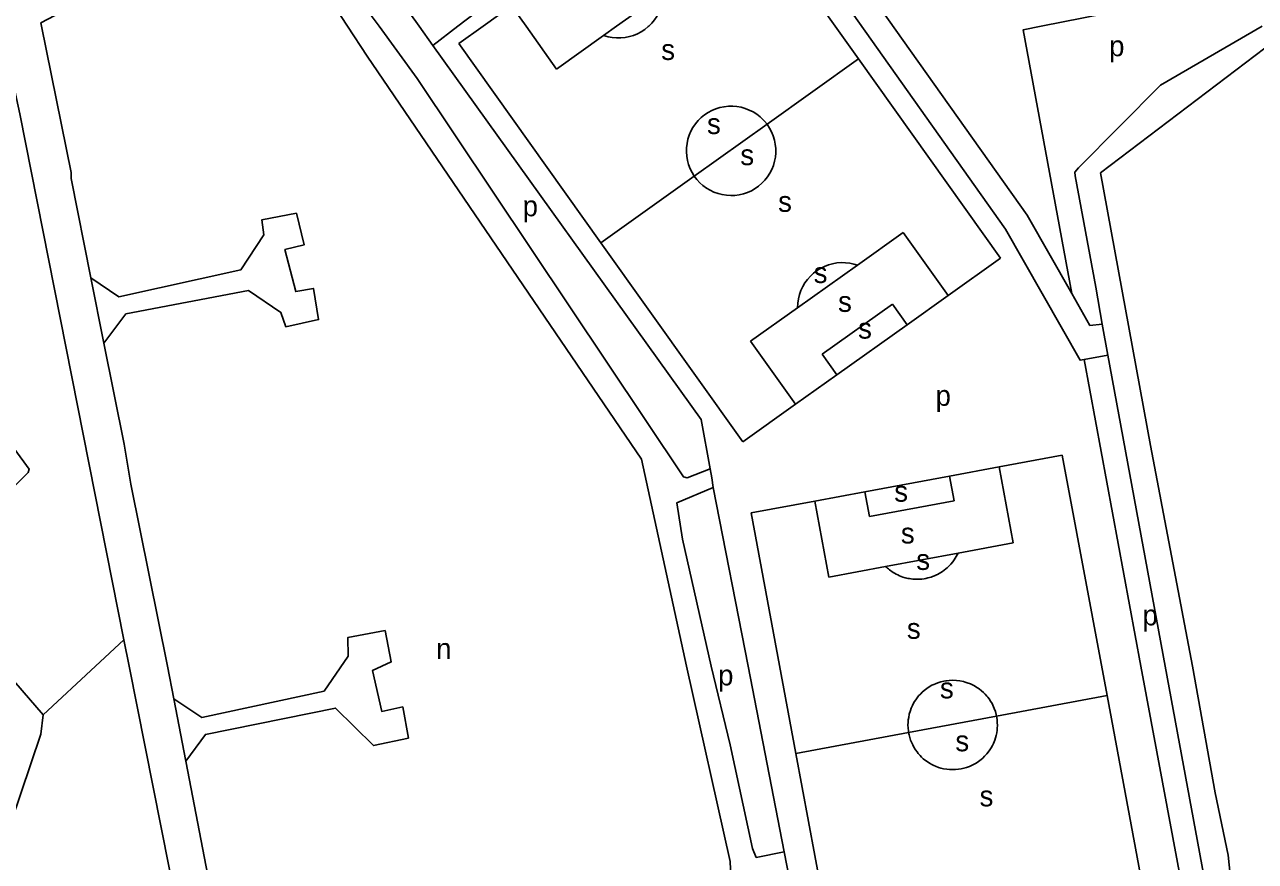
# Model space of a CAD drawing. Extents: x 160204 to 161526, y 379528 to 381793.
# Drawn here: x 160863 to 161102.1, y 380062.1 to 380224.6 of the extents above; entities that cross this region are included whole.
import ezdxf

# ---------------------------------------------------------------- set-up
doc = ezdxf.new("R2010")
doc.units = 0
doc.layers.add('BLT_Basislijn', color=7, linetype='Continuous')
doc.layers.add('BLT_Centroide', color=7, linetype='Continuous')

msp = doc.modelspace()

# ---------------------------------------------------------------- linework, layer by layer
at = {"layer": 'BLT_Basislijn'}
for p, q in [((160999.97, 380260.47), (161053.56, 380184.93)), ((160997.43, 380256.65), (161020.47, 380224.32)), ((161009.34, 380255.9), (161057.78, 380187.62)), ((160931.83, 380224.32), (160911.04, 380252.7)), ((161060.45, 380224.32), (161136.14, 380239.36)), ((160977.98, 380224.32), (160987.1, 380230.82)), ((160957.6, 380228.26), (160952.08, 380224.32)), ((160957.6, 380228.26), (160960.4, 380224.32)), ((160866.24, 380224.32), (160866.11, 380224.96)), ((160939.63, 380224.32), (160942.3, 380220.6)), ((160947.16, 380224.32), (160942.3, 380220.6)), ((160952.08, 380224.32), (160947.37, 380220.97)), ((160960.4, 380224.32), (160966.33, 380216.01)), ((160975.46, 380222.53), (160977.98, 380224.32)), ((161020.47, 380224.32), (161025.01, 380217.97)), ((160966.33, 380216.01), (160975.46, 380222.53)), ((160947.37, 380220.97), (160974.94, 380182.28)), ((161007.21, 380205.28), (161025.01, 380217.97)), ((161052.58, 380179.28), (161025.01, 380217.97)), ((160993.07, 380195.21), (161007.21, 380205.28)), ((160974.94, 380182.28), (160993.07, 380195.21)), ((161066.43, 380172.4), (161057.78, 380187.62)), ((161024.79, 380177.94), (161033.67, 380184.27)), ((161042.4, 380172.03), (161033.67, 380184.27)), ((161002.51, 380143.6), (160974.94, 380182.28)), ((161052.58, 380179.28), (161042.4, 380172.03)), ((161013.15, 380169.65), (161024.79, 380177.94)), ((161042.4, 380172.03), (161034.42, 380166.34)), ((161004.01, 380163.13), (161013.15, 380169.65)), ((161017.94, 380160.63), (161031.56, 380170.34)), ((161034.42, 380166.34), (161031.56, 380170.34)), ((161034.42, 380166.34), (161020.8, 380156.63)), ((161073.45, 380160.43), (161072.34, 380166.45)), ((161012.74, 380150.89), (161004.01, 380163.13)), ((161020.8, 380156.63), (161017.94, 380160.63)), ((161068.83, 380159.58), (161073.45, 380160.43)), ((161020.8, 380156.63), (161012.74, 380150.89)), ((161012.74, 380150.89), (161002.51, 380143.6)), ((161064.57, 380141.04), (161052.28, 380138.76)), ((161064.57, 380141.04), (161073.27, 380094.34)), ((160996.46, 380136.6), (160996.18, 380138.38)), ((161052.28, 380138.76), (161042.65, 380136.96)), ((161052.28, 380138.76), (161055.04, 380123.97)), ((160996.74, 380134.74), (160996.46, 380136.6)), ((161042.65, 380136.96), (161026.21, 380133.9)), ((161042.65, 380136.96), (161043.55, 380132.13)), ((161026.21, 380133.9), (161016.48, 380132.09)), ((161026.21, 380133.9), (161027.1, 380129.07)), ((161016.48, 380132.09), (161004.13, 380129.79)), ((161016.48, 380132.09), (161019.23, 380117.31)), ((161027.1, 380129.07), (161043.55, 380132.13)), ((161004.13, 380129.79), (161012.83, 380083.09)), ((161044.36, 380121.99), (161055.04, 380123.97)), ((161030.26, 380119.36), (161044.36, 380121.99)), ((161019.23, 380117.31), (161030.26, 380119.36)), ((161051.78, 380090.34), (161073.27, 380094.34)), ((161081.96, 380047.64), (161073.27, 380094.34)), ((161034.72, 380087.16), (161051.78, 380090.34)), ((161012.83, 380083.09), (161034.72, 380087.16)), ((161021.52, 380036.39), (161012.83, 380083.09)), ((161010.55, 380063.98), (161011.49, 380058.99))]:
    msp.add_line(p, q, dxfattribs=at)
for points in [[(160996.92, 380260.88), (160954.42, 380229.9), (160947.16, 380224.32)], [(160911.04, 380252.7), (160916.99, 380254.43), (160917.69, 380254.34), (160918.83, 380253.33), (160939.63, 380224.32)], [(160925.74, 380224.32), (160922.26, 380229.65), (160911.89, 380243.12), (160908.64, 380246.11), (160906.06, 380245.97), (160866.11, 380224.96)], [(160984.23, 380224.32), (160984.82, 380224.92), (160985.35, 380225.56), (160985.82, 380226.25), (160986.22, 380226.99), (160986.55, 380227.76), (160986.8, 380228.56), (160986.98, 380229.38), (160987.07, 380230.21), (160987.1, 380230.82)], [(160882.24, 380105.15), (160862.06, 380207.34), (160858.37, 380224.32)], [(160875.87, 380175.47), (160872.02, 380194.78), (160872.02, 380195.89), (160866.24, 380224.32)], [(160918.29, 379956.68), (160978.67, 379970.4), (160981.76, 379971.99), (160983.39, 379973.19), (160985.73, 379975.8), (160987, 379978.19), (160998.45, 380005.86), (161000.28, 380014.12), (161001.44, 380030.18), (161000.06, 380062.07), (160991.56, 380100), (160982.83, 380140.2), (160929.54, 380218.51), (160925.74, 380224.32)], [(160996.18, 380138.38), (160991.69, 380136.63), (160990.96, 380136.78), (160939.27, 380214.17), (160931.83, 380224.32)], [(160975.46, 380222.53), (160976.33, 380222.28), (160977.16, 380222.12), (160977.99, 380222.05), (160978.83, 380222.06), (160979.66, 380222.15), (160980.48, 380222.31), (160981.28, 380222.55), (160982.05, 380222.87), (160982.79, 380223.26), (160983.49, 380223.72), (160984.14, 380224.25), (160984.23, 380224.32)], [(161066.43, 380172.4), (161056.98, 380223.63), (161060.45, 380224.32)], [(161072.34, 380166.45), (161071.08, 380173.66), (161067.06, 380195.3), (161067.03, 380195.98), (161067.73, 380196.79), (161083.66, 380212.87), (161103.4, 380224.32)], [(161113.04, 380224.32), (161105.82, 380221.49), (161072.03, 380195.82), (161081.69, 380142.89), (161089.85, 380100), (161094.29, 380075.45), (161096.83, 380063.3), (161098.08, 380050.73), (161097.61, 380024.93), (161098.88, 379999.01), (161101.9, 379974.84)], [(160942.3, 380220.6), (160994.4, 380147.94), (160996.18, 380138.38)], [(160836.77, 380214.56), (160843.28, 380206.42), (160840.62, 380204.11), (160826.58, 380193.47), (160824.98, 380191.91), (160825.03, 380191.51), (160863.88, 380138.32), (160863.68, 380137.65), (160845.17, 380119.25), (160844.63, 380118.14), (160843.56, 380117.04), (160858.44, 380100), (160866.6, 380090.55)], [(161006.48, 380206.15), (161005.88, 380206.72), (161005.22, 380207.23), (161004.51, 380207.67), (161003.77, 380208.05), (161002.99, 380208.35), (161002.19, 380208.58), (161001.37, 380208.73), (161000.54, 380208.8), (160999.71, 380208.79), (160998.88, 380208.7), (160998.06, 380208.53), (160997.27, 380208.28), (160996.5, 380207.96), (160995.77, 380207.57), (160995.07, 380207.1), (160994.43, 380206.58), (160993.84, 380205.99), (160993.3, 380205.35), (160992.83, 380204.66), (160992.43, 380203.93), (160992.1, 380203.17), (160991.85, 380202.37), (160991.67, 380201.56), (160991.57, 380200.73), (160991.55, 380199.9), (160991.61, 380199.07), (160991.75, 380198.25), (160991.97, 380197.44), (160992.27, 380196.66), (160992.64, 380195.92), (160993.07, 380195.21)], [(160993.07, 380195.21), (160993.58, 380194.54), (160994.14, 380193.93), (160994.76, 380193.38), (160995.43, 380192.88), (160996.15, 380192.46), (160996.9, 380192.1), (160997.69, 380191.82), (160998.49, 380191.61), (160999.32, 380191.49), (161000.15, 380191.44), (161000.98, 380191.47), (161001.81, 380191.58), (161002.62, 380191.77), (161003.41, 380192.04), (161004.17, 380192.38), (161004.89, 380192.8), (161005.57, 380193.28), (161006.21, 380193.82), (161006.78, 380194.42), (161007.3, 380195.07), (161007.75, 380195.78), (161008.13, 380196.52), (161008.44, 380197.29), (161008.67, 380198.09), (161008.83, 380198.91), (161008.91, 380199.74), (161008.9, 380200.57), (161008.82, 380201.4), (161008.66, 380202.22), (161008.42, 380203.01), (161008.1, 380203.79), (161007.71, 380204.52), (161007.21, 380205.28)], [(161007.21, 380205.28), (161006.74, 380205.87), (161006.48, 380206.15)], [(160875.87, 380175.47), (160881.27, 380171.79), (160904.99, 380177.03), (160909.48, 380183.79), (160909.06, 380186.72), (160915.8, 380188), (160917.26, 380181.85), (160913.55, 380180.97), (160915.66, 380172.79), (160919.09, 380173.41), (160920.1, 380167.33), (160913.75, 380165.94), (160912.77, 380168.74), (160906.5, 380173.01), (160882.66, 380168.46), (160878.4, 380162.77)], [(161068.83, 380159.58), (161068.02, 380159.47), (161053.56, 380184.93)], [(161013.15, 380169.65), (161013.2, 380170.55), (161013.32, 380171.38), (161013.53, 380172.19), (161013.81, 380172.98), (161014.16, 380173.74), (161014.58, 380174.46), (161015.08, 380175.14), (161015.63, 380175.76), (161016.24, 380176.34), (161016.9, 380176.85), (161017.61, 380177.29), (161018.36, 380177.67), (161019.14, 380177.97), (161019.95, 380178.2), (161020.77, 380178.34), (161021.6, 380178.41), (161022.44, 380178.4), (161023.27, 380178.31), (161024.09, 380178.14), (161024.79, 380177.94)], [(160878.4, 380162.77), (160875.87, 380175.47)], [(161066.43, 380172.4), (161069.94, 380166.22), (161072.34, 380166.45)], [(160891.97, 380093.66), (160890.76, 380100), (160883.62, 380135.36), (160882.31, 380143.16), (160878.4, 380162.77)], [(161092.51, 380036.64), (161091.14, 380039.36), (161079.84, 380100), (161068.83, 380159.58)], [(161092.51, 380036.64), (161093.27, 380052.99), (161084.55, 380100), (161073.45, 380160.43)], [(161010.55, 380063.98), (161005.13, 380062.86), (161004.4, 380064.63), (161000.07, 380084.75), (160996.35, 380100), (160990.81, 380124.7), (160989.7, 380131.75), (160996.74, 380134.74)], [(161010.55, 380063.98), (161003.58, 380100), (160996.74, 380134.74)], [(161030.26, 380119.36), (161030.48, 380119.16), (161030.62, 380119.04), (161030.78, 380118.9), (161030.98, 380118.74), (161031.26, 380118.53), (161031.47, 380118.38), (161031.73, 380118.22), (161031.98, 380118.07), (161032.27, 380117.91), (161032.6, 380117.74), (161032.92, 380117.59), (161033.28, 380117.45), (161033.61, 380117.34), (161034.02, 380117.21), (161034.32, 380117.14), (161034.59, 380117.07), (161034.86, 380117.03), (161035.21, 380116.97), (161035.56, 380116.93), (161035.98, 380116.9), (161036.26, 380116.9), (161036.61, 380116.9), (161036.93, 380116.92), (161037.27, 380116.95), (161037.73, 380117.01), (161038.06, 380117.06), (161038.48, 380117.16), (161038.75, 380117.23), (161039.07, 380117.32), (161039.34, 380117.42), (161039.73, 380117.57), (161040.12, 380117.75), (161040.34, 380117.85), (161040.67, 380118.03), (161040.97, 380118.21), (161041.3, 380118.43), (161041.62, 380118.65), (161041.93, 380118.9), (161042.19, 380119.12), (161042.38, 380119.29), (161042.65, 380119.56), (161042.93, 380119.86), (161043.29, 380120.3), (161043.55, 380120.66), (161043.77, 380121), (161044.36, 380121.99)], [(160891.97, 380093.66), (160897.38, 380090.04), (160921.15, 380095.16), (160925.84, 380101.99), (160925.8, 380105.62), (160933, 380106.95), (160934.21, 380100.84), (160930.58, 380099.21), (160932.37, 380091.22), (160936.43, 380092.1), (160937.55, 380086.06), (160930.78, 380084.61), (160923.39, 380091.87), (160898.1, 380086.78), (160894.3, 380081.57)], [(160882.24, 380105.15), (160876.76, 380100), (160866.6, 380090.55)], [(160916.02, 379935.16), (160883.29, 380100), (160882.24, 380105.15)], [(161034.72, 380087.16), (161034.67, 380087.48), (161034.62, 380087.99), (161034.6, 380088.62), (161034.61, 380089.06), (161034.65, 380089.61), (161034.73, 380090.08), (161034.85, 380090.69), (161035.06, 380091.4), (161035.23, 380091.85), (161035.47, 380092.4), (161035.69, 380092.81), (161035.87, 380093.13), (161036.11, 380093.5), (161036.38, 380093.87), (161036.67, 380094.23), (161037.09, 380094.68), (161037.35, 380094.95), (161037.73, 380095.28), (161038.25, 380095.68), (161038.73, 380096), (161039.24, 380096.3), (161039.61, 380096.48), (161039.95, 380096.62), (161040.41, 380096.8), (161041, 380096.99), (161041.57, 380097.11), (161041.92, 380097.17), (161042.08, 380097.2), (161042.6, 380097.26), (161043.25, 380097.28), (161044.04, 380097.25), (161044.67, 380097.17), (161045.36, 380097.04), (161045.73, 380096.94), (161046.12, 380096.81), (161046.72, 380096.58), (161047.41, 380096.24), (161048.1, 380095.83), (161048.4, 380095.61), (161048.87, 380095.25), (161049.27, 380094.89), (161049.61, 380094.56), (161049.93, 380094.19), (161050.09, 380093.99), (161050.35, 380093.65), (161050.63, 380093.23), (161050.92, 380092.74), (161051.22, 380092.12), (161051.37, 380091.78), (161051.57, 380091.21), (161051.72, 380090.64), (161051.78, 380090.34)], [(160894.3, 380081.57), (160891.97, 380093.66)], [(160866.6, 380090.55), (160866.14, 380086.8), (160858.4, 380063.96), (160836.31, 380050.55)], [(161051.78, 380090.34), (161051.85, 380090.01), (161051.9, 380089.64), (161051.95, 380089.16), (161051.96, 380088.46), (161051.95, 380088.06), (161051.91, 380087.6), (161051.83, 380087.05), (161051.71, 380086.53), (161051.6, 380086.13), (161051.44, 380085.62), (161051.2, 380085.02), (161050.99, 380084.61), (161050.74, 380084.14), (161050.48, 380083.74), (161050.17, 380083.31), (161049.91, 380082.99), (161049.46, 380082.51), (161049.13, 380082.18), (161048.79, 380081.89), (161048.31, 380081.53), (161047.82, 380081.21), (161047.07, 380080.79), (161046.53, 380080.55), (161045.98, 380080.35), (161045.46, 380080.2), (161044.92, 380080.07), (161044.4, 380079.99), (161043.84, 380079.93), (161043.4, 380079.92), (161043.01, 380079.92), (161042.64, 380079.94), (161042.12, 380080), (161041.51, 380080.09), (161040.98, 380080.23), (161040.53, 380080.36), (161039.96, 380080.57), (161039.62, 380080.73), (161039.24, 380080.92), (161038.8, 380081.16), (161038.31, 380081.48), (161037.97, 380081.73), (161037.57, 380082.05), (161037.25, 380082.35), (161036.94, 380082.66), (161036.58, 380083.08), (161036.35, 380083.36), (161036.08, 380083.75), (161035.76, 380084.26)], [(161035.76, 380084.26), (161035.51, 380084.73), (161035.27, 380085.24), (161035.1, 380085.68), (161034.94, 380086.18), (161034.81, 380086.67), (161034.72, 380087.16)], [(160906.32, 380018.98), (160894.3, 380081.57)]]:
    msp.add_lwpolyline(points, dxfattribs=at)

# ---------------------------------------------------------------- texts
at = {"layer": 'BLT_Centroide'}
for s, p in [('p', (161073.68, 380218.5)), ('s', (160986.66, 380217.78)), ('s', (160995.56, 380203.39)), ('s', (161002.03, 380197.34)), ('p', (160959.74, 380187.41)), ('s', (161009.37, 380188.27)), ('s', (161016.28, 380174.45)), ('s', (161021.02, 380168.84)), ('s', (161024.91, 380163.65)), ('p', (161039.96, 380150.59)), ('s', (161031.93, 380131.97)), ('s', (161033.22, 380123.85)), ('s', (161036.21, 380118.72)), ('p', (161080.16, 380107.94)), ('s', (161034.39, 380105.33)), ('n', (160942.93, 380101.43)), ('p', (160997.72, 380096.28)), ('s', (161040.81, 380093.77)), ('s', (161043.81, 380083.49)), ('s', (161048.51, 380072.79))]:
    msp.add_text(s, height=4, dxfattribs=at).set_placement(p)

doc.saveas('drawing.dxf')
